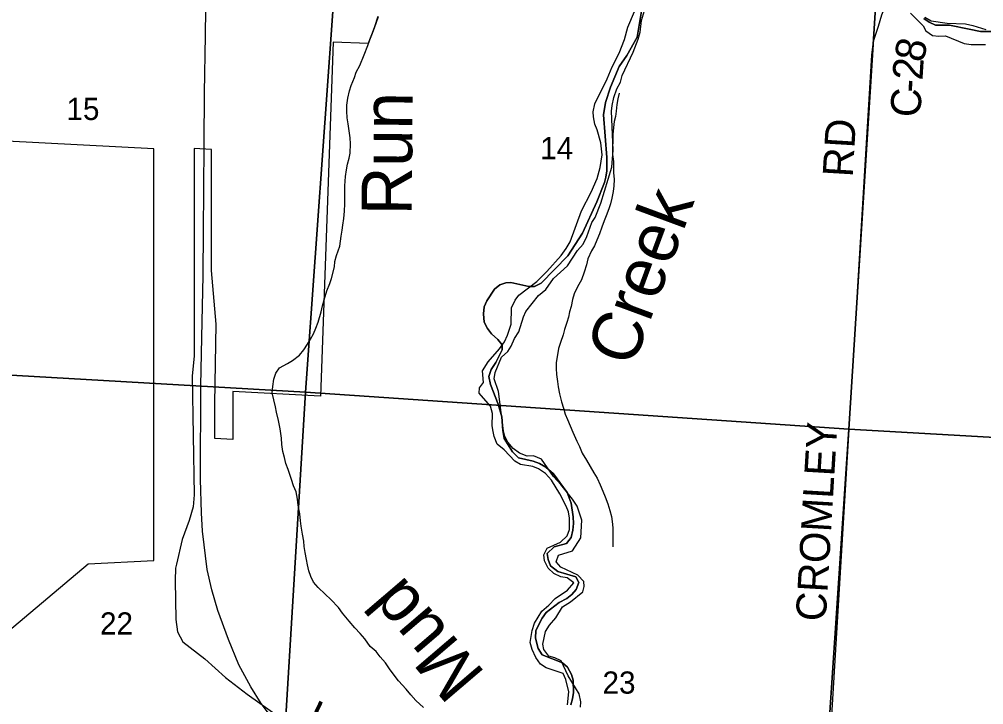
# Model space of a CAD drawing. Extents: x 1643459 to 2064572, y 425441 to 780708.
# Drawn here: x 1829594 to 1839200, y 616295 to 623125 of the extents above; entities that cross this region are included whole.
import ezdxf

# ---------------------------------------------------------------- set-up
doc = ezdxf.new("R2010")
doc.units = 0
for name, color, linetype in [('GM_X_Adjacent_County', 7, 'Continuous'), ('GM_X_City_Street', 7, 'Continuous'), ('GM_X_Interchange_Ramps', 7, 'Continuous'), ('GM_X_Minor_Lake', 7, 'Continuous'), ('GM_X_Rail_Line_Text', 7, 'Continuous'), ('GM_X_Section_Text', 7, 'Continuous'), ('GM_X_State_Route', 7, 'Continuous'), ('GM_X_State_Shield', 7, 'Continuous'), ('GM_X_Unincorporated_Text', 7, 'Continuous'), ('GM_X_US_Route', 7, 'Continuous'), ('RD_X_Wall', 7, 'Continuous')]:
    doc.layers.add(name, color=color, linetype=linetype)

msp = doc.modelspace()

# ---------------------------------------------------------------- linework, layer by layer
at = {"layer": 'GM_X_City_Street'}
for points in [[(1835802.1, 623266), (1835748.5, 622945.2), (1835647.4, 622765), (1835570.7, 622652.9), (1835483.5, 622448.6), (1835432.6, 622294.3), (1835414, 622171.9), (1835446.2, 621748.3), (1835447.7, 621613.9), (1835437.3, 621551.7), (1835423.1, 621497.6), (1835346, 621305.2), (1835204.1, 620992.8), (1835056.6, 620768.6), (1834792.6, 620494.8), (1834726.2, 620461), (1834670, 620463.2), (1834489.6, 620502.1), (1834439.5, 620500.3), (1834379.2, 620480.5), (1834326.8, 620434.6), (1834250, 620318.5), (1834225.7, 620258.4), (1834219.4, 620190.2), (1834225, 620105.9), (1834256.8, 620045.5), (1834298.7, 619991.2), (1834360.7, 619934.7), (1834404.6, 619882.3), (1834404.4, 619830.1), (1834339.6, 619704), (1834293.1, 619635.9), (1834270.8, 619565.8), (1834286.5, 619487.4), (1834365.8, 619290.4), (1834401.4, 619163.8), (1834410.8, 619027.3), (1834424.5, 618946.9), (1834508.2, 618814.1), (1834568.1, 618753.6), (1834714.4, 618720.9), (1834774.5, 618698.5), (1834840.6, 618662.1), (1834916.6, 618595.5), (1835052.2, 618410.3), (1835091.8, 618303.7), (1835111.3, 618167.2), (1835113, 618100.9), (1835108.7, 618034.7), (1835090.3, 617960.5), (1835045.9, 617900.5), (1834923.3, 617868.9), (1834852.8, 617803), (1834860.6, 617742.7), (1834886.4, 617680.4), (1834958.4, 617623.9), (1835136.7, 617568.9), (1835166.5, 617512.6), (1835142.2, 617444.4), (1835097.8, 617392.4), (1835047.5, 617354.5), (1834971, 617314.7), (1834842.2, 617212.9), (1834801.8, 617158.9), (1834739, 617034.7), (1834736.7, 616958.4), (1834762.3, 616855.9), (1834802.2, 616793.5), (1835004.5, 616712.4), (1835056.4, 616670), (1835096.2, 616595.5), (1835110, 616541.3), (1835113.5, 616416.8), (1835105.2, 616352.6), (1835086.9, 616294.5)], [(1835086.9, 616294.5), (1835105.2, 616352.6), (1835113.5, 616416.8), (1835110, 616541.3), (1835096.2, 616595.5), (1835056.4, 616670), (1835004.5, 616712.4), (1834802.2, 616793.5), (1834762.3, 616855.9), (1834736.7, 616958.4), (1834739, 617034.7), (1834801.8, 617158.9), (1834842.2, 617212.9), (1834971, 617314.7), (1835047.5, 617354.5), (1835097.8, 617392.4), (1835142.2, 617444.4), (1835166.5, 617512.6), (1835136.7, 617568.9), (1834958.4, 617623.9), (1834886.4, 617680.4), (1834860.6, 617742.7), (1834852.8, 617803), (1834923.3, 617868.9), (1835045.9, 617900.5), (1835090.3, 617960.5), (1835108.7, 618034.7), (1835113, 618100.9), (1835111.3, 618167.2), (1835091.8, 618303.7), (1835052.2, 618410.3), (1834916.6, 618595.5), (1834840.6, 618662.1), (1834774.5, 618698.5), (1834714.4, 618720.9), (1834568.1, 618753.6), (1834508.2, 618814.1), (1834424.5, 618946.9), (1834410.8, 619027.3), (1834401.4, 619163.8), (1834365.8, 619290.4), (1834286.5, 619487.4), (1834270.8, 619565.8), (1834293.1, 619635.9), (1834339.6, 619704), (1834404.4, 619830.1), (1834404.6, 619882.3), (1834360.7, 619934.7), (1834298.7, 619991.2), (1834256.8, 620045.5), (1834225, 620105.9), (1834219.4, 620190.2), (1834225.7, 620258.4), (1834250, 620318.5), (1834326.8, 620434.6), (1834379.2, 620480.5), (1834439.5, 620500.3), (1834489.6, 620502.1), (1834670, 620463.2), (1834726.2, 620461), (1834792.6, 620494.8), (1835056.6, 620768.6), (1835204.1, 620992.8), (1835346, 621305.2), (1835423.1, 621497.6), (1835437.3, 621551.7), (1835447.7, 621613.9), (1835446.2, 621748.3), (1835414, 622171.9), (1835432.6, 622294.3), (1835483.5, 622448.6), (1835570.7, 622652.9), (1835647.4, 622765), (1835748.5, 622945.2), (1835802.1, 623266)], [(1839283.1, 623002.5), (1839167.9, 623002.5), (1839056.3, 623026.9), (1838860.9, 623065.3), (1838721.4, 623065.3), (1838658.6, 623096.7), (1838602.7, 623131.6)], [(1838602.7, 623131.6), (1838658.6, 623096.7), (1838721.4, 623065.3), (1838860.9, 623065.3), (1839056.3, 623026.9), (1839167.9, 623002.5), (1839283.1, 623002.5)]]:
    msp.add_lwpolyline(points, dxfattribs=at)
at = {"layer": 'GM_X_Minor_Lake'}
msp.add_lwpolyline([(1838295.3, 623507.5), (1838285.2, 623456.1), (1838247.4, 623339.1), (1838183.6, 623166.4), (1838147.8, 623052), (1838100, 622903.4), (1838084.3, 622768.9), (1837635, 615362.4), (1837553.3, 614083.1), (1837539.4, 613880.4), (1837532.9, 613820.2), (1837499.6, 613782.2), (1837469.1, 613757.3), (1837433.9, 613736.9), (1835907.7, 613840.6)], dxfattribs=at)
at = {"layer": 'GM_X_Rail_Line_Text'}
for points in [[(1833167.1, 623153), (1833128.5, 623038.8), (1833102.1, 622968.7), (1833081.8, 622918.6), (1833069.6, 622885.1), (1832719.3, 622896.2), (1832596.1, 619368.8), (1831720.3, 619414.7), (1831720.3, 618937.7), (1831540.6, 618947.1), (1831540.6, 619297.1), (1831554.3, 620086), (1831507.5, 620620.9), (1831507.5, 621827.9), (1831337.8, 621836.8), (1831337.8, 620770.8), (1831337.8, 619770.8), (1831316.6, 619570), (1831337.3, 618387.1), (1831326.7, 618265.6), (1831285.1, 618129.8), (1831217.1, 617942.8), (1831159.9, 617695.3), (1831150.5, 617654.4), (1831146.2, 617531.5), (1831153, 617143.5), (1831170.1, 617021.7), (1831223.1, 616922), (1831441.4, 616751.4), (1831647.3, 616566.1), (1831864.6, 616400), (1832322.1, 616074)], [(1829009.7, 616629.8), (1830282.1, 617697.5), (1830935.2, 617731.7), (1830935.2, 621832.7), (1827176.4, 622029.7)]]:
    msp.add_lwpolyline(points, dxfattribs=at)
at = {"layer": 'GM_X_State_Route'}
for points in [[(1832831.4, 624779), (1832445.6, 619408.6), (1827728.7, 619680.9), (1827930.5, 625060.1)], [(1838195.8, 624403.2), (1837858, 619040.6), (1832445.6, 619408.6), (1832831.4, 624779)], [(1843542.1, 624017.5), (1843247.1, 619224.7), (1843212.7, 618736.9), (1837858, 619040.6), (1838195.8, 624403.2)], [(1832445.6, 619408.6), (1837858, 619040.6), (1837502.5, 613740.2), (1832124, 614096)], [(1843212.7, 618736.9), (1842906.5, 613710.2), (1842889.1, 613414.2), (1837502.5, 613740.2), (1837858, 619040.6)]]:
    msp.add_lwpolyline(points, close=True, dxfattribs=at)
msp.add_lwpolyline([(1827728.7, 619680.9), (1832445.6, 619408.6), (1832124, 614096), (1830756.5, 614194.6), (1830662.7, 614251.1), (1830565.1, 614325.5), (1830491.5, 614405.9), (1830463.7, 614458), (1830441.9, 614502.1), (1830430.1, 614540.2), (1830412.4, 614600.3), (1830400.8, 614680.3), (1830377.2, 614770.4), (1830296.2, 614972.9), (1830254.6, 615055), (1830193.1, 615163.3), (1830147.4, 615225.6), (1830082, 615351.9), (1829952.8, 615522.5), (1829901.2, 615592.8), (1829740.2, 615807.5), (1829497.7, 616114.7)], dxfattribs=at)
at = {"layer": 'GM_X_Unincorporated_Text'}
for points in [[(1835156.5, 617586.1), (1834988.3, 617665.1), (1834942.4, 617717.5), (1834964.8, 617785.7), (1835105.4, 617827.2), (1835186.2, 617957.3), (1835197.1, 618133.9), (1835151.5, 618272.6), (1835105.7, 618343.1), (1834990, 618490.1), (1834916.1, 618570.7), (1834794.4, 618741.8), (1834716.3, 618774.3), (1834652.1, 618770.6), (1834576, 618801), (1834512, 618847.4), (1834462.1, 618911.9), (1834430.3, 618970.2), (1834416.5, 619024.5), (1834368.1, 619416.1), (1834324.5, 619542.7), (1834332.8, 619604.9), (1834397.7, 619757.2), (1834462.1, 619815.1), (1834494.5, 619867.1), (1834526.9, 619945.3), (1834571.3, 620011.3), (1834616.2, 620159.6), (1834640.5, 620211.7), (1834765.6, 620371.7), (1834840.1, 620431.6), (1834914.8, 620541.7), (1835053.8, 620667.5), (1835154.8, 620821.6), (1835209.3, 620883.6), (1835247.8, 620959.7), (1835298.5, 621100), (1835328.9, 621150), (1835385.7, 621292.3), (1835495.6, 621653), (1835510.4, 621821.6), (1835492.1, 622211), (1835500.4, 622265.1), (1835516.8, 622345.3), (1835547.3, 622431.5), (1835581.7, 622499.6), (1835600, 622563.7), (1835709.4, 622796.1), (1835758.1, 622926.3), (1835778.5, 622996.5), (1835793.1, 623112.8), (1835852.2, 623313.2)], [(1835076.3, 618042.1), (1835074.7, 618154.5), (1835065, 618216.8), (1835043.2, 618273.1), (1834979.5, 618397.8), (1834895.8, 618532.7), (1834835.9, 618599.2), (1834765.9, 618645.6), (1834709.8, 618667.9), (1834585.5, 618688.5), (1834529.5, 618720.9), (1834423.6, 618833.8), (1834355.7, 618892.3), (1834323.9, 618966.7), (1834314.1, 619016.9), (1834304.3, 619073.1), (1834306.9, 619197.6), (1834287.1, 619269.9), (1834175.4, 619400.9), (1834179.6, 619453), (1834218, 619505), (1834208.5, 619623.5), (1834263, 619711.6), (1834378, 619841.5), (1834426.4, 619911.6), (1834456.8, 619977.7), (1834493.4, 620087.9), (1834496.2, 620248.5), (1834532.6, 620324.6), (1834571, 620376.6), (1834748.1, 620512.3), (1834848.9, 620610.2), (1834990.1, 620772.2), (1835040.6, 620842.2), (1835083, 620908.2), (1835194.7, 621214.8), (1835291.9, 621401), (1835350.7, 621539.3), (1835381.2, 621647.5), (1835399.9, 621773.9), (1835386.4, 621894.4), (1835350.8, 622025), (1835327, 622081.2), (1835313.3, 622151.6), (1835309.5, 622201.8), (1835327.9, 622284), (1835449.4, 622530.3), (1835498.1, 622650.5), (1835568.9, 622786.7), (1835623.7, 622924.9), (1835656.3, 623047.2), (1835723.2, 623201.4)], [(1838472.2, 623187.5), (1838598, 623060.5), (1838623.9, 623010.2), (1838689.9, 622963.8), (1838754.1, 622957.5), (1838820.3, 622961.2), (1839006.5, 622882.1), (1839074.7, 622873.8), (1839217.2, 622873.2)], [(1838612.4, 623144.7), (1838676.5, 623110.3), (1838836.9, 623087.6), (1839017.5, 623078.7), (1839093.6, 623062.3), (1839219.9, 623023.7)], [(1834861.8, 617655.7), (1834826.1, 617730.1), (1834818.3, 617788.3), (1834850.7, 617856.4), (1834985.4, 617914), (1835051.9, 617978), (1835076.3, 618042.1)], [(1835056.4, 616293.9), (1835069, 616422.3), (1835037.5, 616544.9), (1835011.7, 616605.2), (1834841.4, 616664.1), (1834787.3, 616698.5), (1834739.5, 616767), (1834703.7, 616845.4), (1834682, 616915.8), (1834702.6, 617034.1), (1834727, 617108.2), (1834797.7, 617226.4), (1834870.2, 617286.3), (1834932.7, 617352.2), (1835053.5, 617438), (1835118, 617510), (1835052, 617558.5), (1834987.9, 617568.8), (1834917.8, 617603.2), (1834861.8, 617655.7)], [(1834939.9, 617161.5), (1835006.6, 617269.6), (1835083.1, 617321.5), (1835205.9, 617421.3), (1835222.2, 617473.4), (1835218.4, 617523.6), (1835156.5, 617586.1)], [(1835182.7, 616271.2), (1835187, 616323.4), (1835171.3, 616403.8), (1835061.7, 616582.9), (1834992.2, 616733.7), (1834930.1, 616762.1), (1834868, 616778.4), (1834818.1, 616846.9), (1834808.3, 616899.1), (1834834.9, 617023.5), (1834875.4, 617087.5), (1834939.9, 617161.5)]]:
    msp.add_lwpolyline(points, dxfattribs=at)
at = {"layer": 'GM_X_US_Route'}
for points in [[(1832882.5, 622410.9), (1832898.8, 622465.1), (1832933.3, 622545.2), (1832949.6, 622597.3), (1832988, 622663.4), (1833028.6, 622769.5), (1833065.1, 622863.7), (1833085.4, 622919.8), (1833105.7, 622969.9), (1833132.1, 623040), (1833170.7, 623154.2)], [(1833619.6, 616268), (1833545.7, 616338.5), (1833493.8, 616393), (1833447.9, 616449.4), (1833372, 616534), (1833288.2, 616642.8), (1833242.4, 616711.2), (1833190.5, 616771.7), (1833148.6, 616824), (1833090.6, 616876.5), (1833036.8, 616951), (1832988.8, 617003.4), (1832936.9, 617061.8), (1832879, 617128.3), (1832815.2, 617206.9), (1832775.3, 617265.2), (1832697.4, 617343.9), (1832641.5, 617398.3), (1832571.5, 617464.8), (1832525.6, 617515.2), (1832497.8, 617571.6), (1832480, 617627.8), (1832466.2, 617688.1), (1832456.4, 617742.4), (1832442.7, 617812.7), (1832432.9, 617870.9), (1832427.1, 617925.1), (1832415.4, 617995.4), (1832401.7, 618075.8), (1832395.9, 618128), (1832388.2, 618198.3), (1832372.5, 618282.7), (1832364.8, 618344.9), (1832351, 618415.2), (1832327.2, 618475.5), (1832305.4, 618537.9), (1832271.8, 618640.4), (1832248, 618698.7), (1832236.2, 618756.9), (1832220.4, 618817.2), (1832210.7, 618887.5), (1832205, 618951.8), (1832191.3, 619044.2), (1832175.6, 619126.5), (1832158, 619210.9), (1832146.2, 619263.1), (1832128.4, 619333.5), (1832112.7, 619403.8), (1832121, 619466), (1832131.3, 619540.2), (1832149.7, 619598.3), (1832186, 619652.3), (1832264.5, 619696.2), (1832314.8, 619726), (1832385.2, 619777.9), (1832429.6, 619831.9), (1832466, 619888), (1832496.3, 619938), (1832524.6, 619992.1), (1832548.9, 620046.2), (1832571.3, 620108.3), (1832599.8, 620208.5), (1832614.1, 620270.7), (1832630.5, 620330.8), (1832656.9, 620419), (1832687.4, 620491.1), (1832703.6, 620541.2), (1832734.2, 620657.5), (1832738.5, 620711.7), (1832754.8, 620771.8), (1832787.3, 620864), (1832799.8, 620962.3), (1832810.1, 621024.5), (1832816.4, 621074.6), (1832826.7, 621140.8), (1832835, 621213), (1832837.4, 621285.2), (1832835.6, 621347.5), (1832838.2, 621465.9), (1832842.6, 621558.2), (1832854.9, 621624.3), (1832865.2, 621680.5), (1832881.5, 621740.6), (1832889.8, 621790.8), (1832892.2, 621883.1), (1832890.5, 621945.3), (1832880.7, 622013.6), (1832869, 622081.9), (1832859.2, 622142.1), (1832855.5, 622208.4), (1832857.8, 622268.6), (1832868.1, 622338.8), (1832882.5, 622410.9)], [(1835569.1, 622389.3), (1835556.9, 622333.1), (1835546.6, 622277), (1835538.3, 622210.8), (1835532, 622156.6), (1835519.7, 622106.5), (1835511.4, 622046.3), (1835507.1, 621976.1), (1835504.9, 621921.9), (1835502.5, 621845.7), (1835504.2, 621777.4), (1835511.9, 621709.2), (1835511.7, 621651), (1835513.5, 621598.8), (1835519.2, 621528.5), (1835514.9, 621466.3), (1835508.6, 621408.1), (1835496.3, 621342), (1835482, 621285.8), (1835465.7, 621235.7), (1835441.3, 621165.6), (1835421, 621115.5), (1835396.7, 621053.4), (1835374.3, 620987.2), (1835345.9, 620923.2), (1835323.6, 620869.1), (1835295.3, 620819), (1835258.8, 620738.9), (1835242.5, 620676.7), (1835220.1, 620606.6), (1835193.7, 620530.4), (1835155.2, 620458.3), (1835122.8, 620388.2), (1835104.5, 620332.1), (1835092.2, 620263.9), (1835073.9, 620209.8), (1835063.6, 620155.7), (1835049.3, 620103.6), (1835024.9, 620035.4), (1835010.6, 619981.3), (1834984.2, 619903.1), (1834965.9, 619843), (1834951.5, 619762.8), (1834941.2, 619704.6), (1834942.9, 619644.4), (1834946.7, 619584.2), (1834954.4, 619515.9), (1834962.2, 619463.7), (1834973.9, 619393.4), (1834993.6, 619313), (1835013.4, 619248.7), (1835031.2, 619190.4), (1835055, 619136.1), (1835082.8, 619073.8), (1835108.7, 619011.4), (1835146.4, 618921), (1835174.2, 618866.6), (1835202, 618802.3), (1835243.9, 618731.9), (1835279.7, 618667.5), (1835317.5, 618605.1), (1835349.4, 618552.8), (1835381.2, 618486.4), (1835407, 618424), (1835428.8, 618365.8), (1835456.6, 618297.4), (1835476.4, 618229), (1835492.2, 618170.8), (1835500, 618120.6), (1835507.7, 618056.3), (1835507.1, 617919.8), (1835504.9, 617869.6)]]:
    msp.add_lwpolyline(points, dxfattribs=at)
at = {"layer": 'RD_X_Wall'}
for points in [[(1831436.9, 621883.3), (1831440.7, 622391.8), (1831449.9, 622962.8), (1831453.6, 623227.1)], [(1831429.4, 621019.6), (1831433.4, 621417.4), (1831436.9, 621883.3)], [(1832118.1, 616153.3), (1832077.4, 616209.4), (1832003.4, 616308.3), (1831902, 616472.8), (1831782.6, 616691.5), (1831676.7, 616943.9), (1831573, 617232.4), (1831512.2, 617439.8), (1831464.9, 617642.7), (1831420.1, 618024), (1831410.2, 618206.3), (1831400.2, 618537.9), (1831403.6, 619474.4), (1831416.4, 620110.7), (1831424.9, 620571.9), (1831429.4, 621019.6)]]:
    msp.add_lwpolyline(points, dxfattribs=at)

# ---------------------------------------------------------------- texts
at = {"layer": 'GM_X_Adjacent_County'}
for s, p in [('15', (1830064.1, 622121.6)), ('14', (1834783, 621731.1)), ('22', (1830398.5, 616994.5)), ('23', (1835403.5, 616405.5))]:
    msp.add_text(s, height=221, rotation=0.00001, dxfattribs=at).set_placement(p)
at = {"layer": 'GM_X_Interchange_Ramps'}
for s, height, rotation, p in [('Run', 500, 89.52075, (1833502.9, 621171.1)), ('Mud', 500.05, 130.51408, (1834246.7, 616604.8))]:
    msp.add_text(s, height=height, rotation=rotation, dxfattribs=at).set_placement(p)
at = {"layer": 'GM_X_Section_Text'}
for s, rotation, p in [('8', 78.96665, (1838600.5, 622685.6)), ('2', 86.38081, (1838590.1, 622511.4)), ('-', 86.57119, (1838582.7, 622388.6)), ('C', 86.60626, (1838568.2, 622142.7)), ('RD', 86.54661, (1837894.9, 621547.1)), ('CROMLEY', 86.61668, (1837626.4, 617120.5)), ('L', 334.62141, (1832425.9, 616077.7))]:
    msp.add_text(s, height=300, rotation=rotation, dxfattribs=at).set_placement(p)
at = {"layer": 'GM_X_State_Shield'}
msp.add_text('Creek', height=500.02, rotation=69.69523, dxfattribs=at).set_placement((1835703.5, 619643.6))

doc.saveas('drawing.dxf')
